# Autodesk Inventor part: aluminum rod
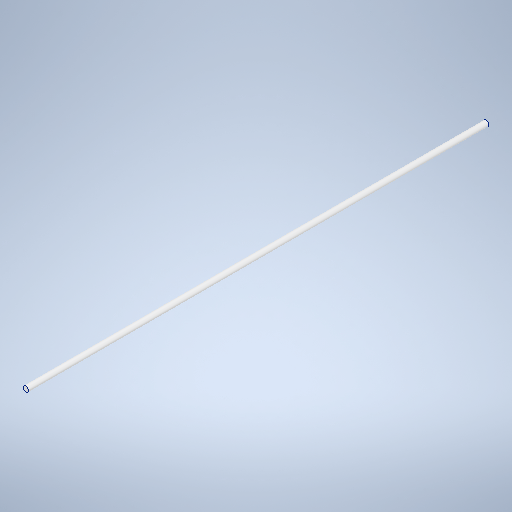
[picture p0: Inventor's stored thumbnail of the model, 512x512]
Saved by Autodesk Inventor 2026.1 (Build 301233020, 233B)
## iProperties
Created: 2026-10
Part Number: aluminum rod
Material: Aluminum 6061
Document SubType Name: Modeling
Designer: hp
Density: 2.7 g/cm^3
Appearance: Aluminum - Flat
Author: hp
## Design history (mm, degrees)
sketch "Sketch1"
  geometry: C1 r 4 at (0, 0); 1 further point
  constraints: 1 centre point, 1 coincident
  dimensions: "d0" = 8 diameter of C1
extrude "Extrusion1" new body sketch "Sketch1" distance "d1" = 670; taper "d2" = 0 deg
body "Solid1"
